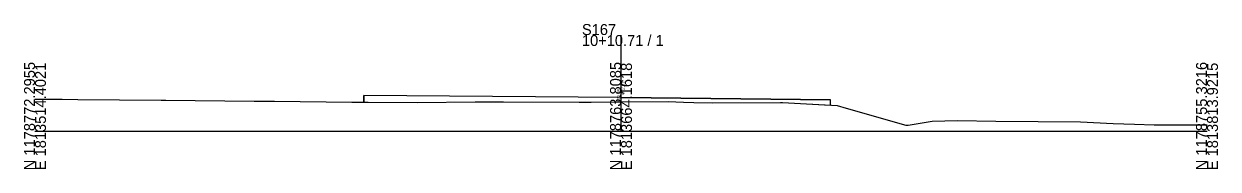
# Model space of a CAD drawing. Extents: x -26 to 6803, y -10 to 1023.
# Drawn here: x 5197.2 to 5502.8, y -9.7 to 27.4 of the extents above; entities that cross this region are included whole.
import ezdxf

# ---------------------------------------------------------------- set-up
doc = ezdxf.new("R2010")
doc.units = 0
for name, color, linetype in [('Default', 7, 'Continuous'), ('RD_GPK_XS_Cell', 7, 'Continuous'), ('RD_XS_ExGround', 7, 'Continuous'), ('RD_XS_Misc_Line', 7, 'Continuous'), ('RD_XS_Pave', 7, 'Continuous'), ('RD_XS_TX_Elev_EX', 7, 'Continuous'), ('RD_XS_TX_Elev_PR', 7, 'Continuous')]:
    doc.layers.add(name, color=color, linetype=linetype)

msp = doc.modelspace()

# ---------------------------------------------------------------- linework, layer by layer
at = {"layer": 'Default'}
for q in [(5284.19, 9.15), (5403.63, 8.02)]:
    msp.add_line((5350, 8.61), q, dxfattribs=at)
at = {"layer": 'RD_GPK_XS_Cell'}
for p, q in [((5350, 0), (5350, 24.56)), ((5200, 0), (5350, 0)), ((5350, 0), (5500, 0))]:
    msp.add_line(p, q, dxfattribs=at)
at = {"layer": 'RD_XS_ExGround'}
msp.add_lwpolyline([(5200, 8.19), (5206.93, 8.13), (5210.99, 8.09), (5232.29, 7.94), (5233.5, 7.93), (5256.14, 7.67), (5261.33, 7.62), (5281.12, 7.4), (5284.28, 7.42), (5285.32, 7.43), (5297.92, 7.36), (5312.63, 7.51), (5319.96, 7.49), (5339.3, 7.43), (5339.7, 7.43), (5340.48, 7.38), (5341.64, 7.39), (5342.33, 7.4), (5350, 7.45), (5362.04, 7.54), (5365.97, 7.38), (5368.61, 7.3), (5373.51, 7.24), (5390.8, 7.34), (5391.37, 7.35), (5397.45, 7.01), (5403.84, 6.65), (5405.29, 6.58), (5407.61, 5.88), (5422.88, 1.49), (5423.5, 1.55), (5427.05, 2.1), (5429.65, 2.58), (5436.17, 2.68), (5445.98, 2.51), (5467.59, 2.41), (5476.01, 1.98), (5481.44, 1.79), (5486.46, 1.61), (5494.56, 1.61), (5500, 1.62)], dxfattribs=at)
at = {"layer": 'RD_XS_Misc_Line'}
msp.add_lwpolyline([(5397.45, 7.01), (5403.63, 6.67), (5403.63, 8.02), (5350, 8.61), (5284.19, 9.15), (5284.19, 7.42), (5284.28, 7.42), (5285.32, 7.43), (5297.92, 7.36), (5312.63, 7.51), (5319.96, 7.49), (5339.3, 7.43), (5339.7, 7.43), (5340.48, 7.38), (5341.64, 7.39), (5342.33, 7.4), (5350, 7.45), (5362.04, 7.54), (5365.97, 7.38), (5368.61, 7.3), (5373.51, 7.24), (5390.8, 7.34), (5391.37, 7.35)], close=True, dxfattribs=at)
msp.add_lwpolyline([(5397.45, 7.01), (5403.63, 6.67), (5403.63, 8.02), (5350, 8.61), (5284.19, 9.15), (5284.19, 7.42), (5284.28, 7.42), (5285.32, 7.43), (5297.92, 7.36), (5312.63, 7.51), (5319.96, 7.49), (5339.3, 7.43), (5339.7, 7.43), (5340.48, 7.38), (5341.64, 7.39), (5342.33, 7.4), (5350, 7.45), (5362.04, 7.54), (5365.97, 7.38), (5368.61, 7.3), (5373.51, 7.24), (5390.8, 7.34), (5391.37, 7.35)], close=True, dxfattribs=at)
msp.add_lwpolyline([(5397.45, 7.01), (5403.63, 6.67), (5403.63, 8.02), (5350, 8.61), (5284.19, 9.15), (5284.19, 7.42), (5284.28, 7.42), (5285.32, 7.43), (5297.92, 7.36), (5312.63, 7.51), (5319.96, 7.49), (5339.3, 7.43), (5339.7, 7.43), (5340.48, 7.38), (5341.64, 7.39), (5342.33, 7.4), (5350, 7.45), (5362.04, 7.54), (5365.97, 7.38), (5368.61, 7.3), (5373.51, 7.24), (5390.8, 7.34), (5391.37, 7.35)], close=True, dxfattribs=at)
msp.add_lwpolyline([(5397.45, 7.01), (5403.63, 6.67), (5403.63, 8.02), (5350, 8.61), (5284.19, 9.15), (5284.19, 7.42), (5284.28, 7.42), (5285.32, 7.43), (5297.92, 7.36), (5312.63, 7.51), (5319.96, 7.49), (5339.3, 7.43), (5339.7, 7.43), (5340.48, 7.38), (5341.64, 7.39), (5342.33, 7.4), (5350, 7.45), (5362.04, 7.54), (5365.97, 7.38), (5368.61, 7.3), (5373.51, 7.24), (5390.8, 7.34), (5391.37, 7.35)], close=True, dxfattribs=at)
msp.add_lwpolyline([(5397.45, 7.01), (5403.63, 6.67), (5403.63, 8.02), (5350, 8.61), (5284.19, 9.15), (5284.19, 7.42), (5284.28, 7.42), (5285.32, 7.43), (5297.92, 7.36), (5312.63, 7.51), (5319.96, 7.49), (5339.3, 7.43), (5339.7, 7.43), (5340.48, 7.38), (5341.64, 7.39), (5342.33, 7.4), (5350, 7.45), (5362.04, 7.54), (5365.97, 7.38), (5368.61, 7.3), (5373.51, 7.24), (5390.8, 7.34), (5391.37, 7.35)], close=True, dxfattribs=at)
at = {"layer": 'RD_XS_Pave'}
for p, q in [((5284.19, 7.42), (5284.19, 9.15)), ((5403.63, 6.67), (5403.63, 8.02))]:
    msp.add_line(p, q, dxfattribs=at)

# ---------------------------------------------------------------- texts
at = {"layer": 'RD_GPK_XS_Cell'}
for s, p in [('S167', (5340, 24.56)), ('10+10.71 / 1', (5340, 21.76))]:
    msp.add_text(s, height=2.8, dxfattribs=at).set_placement(p)
for s, p in [('N 1178772.2955', (5200, -10)), ('E 1813514.4021', (5202.8, -10)), ('N 1178763.8085', (5350, -10)), ('E 1813664.1618', (5352.8, -10)), ('N 1178755.3216', (5500, -10)), ('E 1813813.9215', (5502.8, -10))]:
    msp.add_text(s, height=2.8, rotation=90, dxfattribs=at).set_placement(p)
at = {"layer": 'RD_XS_TX_Elev_EX'}
msp.add_text('671.45', height=0.8, rotation=90, dxfattribs=at).set_placement((5349.86, 7.45))
at = {"layer": 'RD_XS_TX_Elev_PR'}
msp.add_text('672.61', height=0.8, rotation=90, dxfattribs=at).set_placement((5350.9, 9.34))

doc.saveas('drawing.dxf')
